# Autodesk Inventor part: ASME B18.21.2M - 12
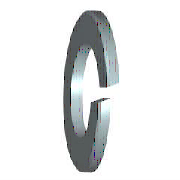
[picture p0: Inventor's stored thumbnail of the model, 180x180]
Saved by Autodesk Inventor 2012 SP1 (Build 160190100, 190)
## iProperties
Created: 2006-02
Part Number: ASME B18.21.2M - 12
Material: Steel, Mild
Description: Heavy Helical Spring Lock Washers
Document SubType Name: Modeling
Standard: ASME B18.21.2M
Designer: Administrator
Standards Organization: ANSI
Language: en-US
Categories: <MemberInstance><Categories><Category DisplayName="Fasteners" InternalName="e4da775c-781d-43d5-af7c-5136215cf5a6" Mnemonic="FSTN"><Category DisplayName="Washers
Density: 7.86 g/cm^3
Author: Administrator
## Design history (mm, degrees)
node "WorkPlane1"
node "WorkPlane3"
workplane "Work Plane3"
node "WorkPlane10"
node "Sketch1"
node "WorkPoint2"
node "Sketch3"
node "WorkPoint1"
sketch "Sketch4"
  geometry: C1 r 10.865 at (0, 0) reference
hole "Hole1" sketch "Sketch4" diameter "d7" = 12.45 (= Diam1); stored, may be unused: countersink angle "d11" = 60 deg, drill point angle "d13" = 118 deg; dims "d8" = 6, "d9" = 4, "d10" = 2, "d12" = 8
node "WorkAxis1"
node "MSC_A1"
node "MSC_PT1"
node "MSC_PT2"
body "Solid1"
extrude "Extrusion1" new body distance "d4" = 3.84 (= ParH); taper "d5" = 0 deg
sketch "Sketch5"
  geometry: L1 (-0.197, 0)-(-1.157, 0); L2 (0.48, -3.84)-(-0.197, 0); L3 (-0.48, -3.84)-(0.48, -3.84); L4 (-1.157, 0)-(-0.48, -3.84); L5 (-6.225, 0)-(6.225, 0) reference; L6 (10.865, -3.84)-(-10.865, -3.84) reference; L7 (0, -4.608)-(0, 0.768) reference
  constraints: 8 end point, 2 collinear, 2 horizontal, 1 parallel
  dimensions: "d15" = 80 deg angle of L4 L1; "d18" = 0.48 distance from line of L3.start L7 (= 0.125 x ParH); "d19" = 0.48 distance from line of L7 L2.start (= 0.125 x ParH)
extrude "Extrusion2" cut sketch "Sketch5" distance "d16" = 10.865 (= 0.5 x Diam2); taper "d17" = 0 deg
node "Sketch2" dims "d3" = 21.73 (= Diam2)
other parameters: "Diam2" = 21.73 [user parameter; used in 4 equation terms], "ParH" = 3.84 [user parameter; used in 4 equation terms], "Diam1" = 12.45 [user parameter; used in 1 equation term], "d0" = -3.84 (computed from ParH), "d1" = -10.865 (computed from Diam2), "d2" = 25 (derived), "d6" = 0, "d14" = 80 deg (derived), "d20" = 10.865 (= 0.5 x Diam2), "d23" = 0, "d24" = 0, "d26" = 0, "d27" = 0, "d28" = 0
